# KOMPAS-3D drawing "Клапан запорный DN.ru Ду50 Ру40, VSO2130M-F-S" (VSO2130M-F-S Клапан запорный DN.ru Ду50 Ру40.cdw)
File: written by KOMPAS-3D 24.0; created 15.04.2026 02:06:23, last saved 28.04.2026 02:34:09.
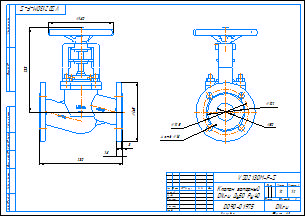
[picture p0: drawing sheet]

Document properties: Автор: DN.ru; Форматы листов документа: A3; Полное имя файла: VSO2130M-F-S Клапан запорный DN.ru Ду50 Ру40.m3d; Масса: 12; Наименование: Клапан запорный DN.ru Ду50 Ру40; Количество листов документа: 1; Примечание: D090-01975

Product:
- Part/product: Клапан запорный DN.ru Ду50 Ру40  | designation VSO2130M-F-S
    Масса: 12
    Раздел спецификации: Прочие изделия
    Примечание: D090-01975

Views: Вид 1, Вид:1, Проекционный вид 2
Referenced files in C:\Работа\VSO2130M-F-S Клапан запорный DN.ru\DN20\: VSO2130M-F-S DN20 PN40  Клапан запорный сильфонный DN.ru.m3d
Referenced files in C:\Работа\VSO2130M-F-S Клапан запорный DN.ru\DN50\: VSO2130M-F-S Клапан запорный DN.ru Ду50 Ру40.m3d
Referenced files in C:\Program Files\ASCON\KOMPAS-3D v24\Templates\: Чертеж_DN.ru.cdt
Referenced files in C:\Работа\ГОТОВЫЕ ИСХОДНИКИ\VSO2130M-F-S Клапан запорный сильфонный DN.ru Ду15-100 Ру40\DN50\: VSO2130M-F-S Клапан запорный DN.ru Ду50 Ру40.m3d
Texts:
  VSO2130M-F-S
  Чертеж_DN.ru.cdt
  Клапан запорный
  DN.ru Ду50 Ру40
  Клапан запорный DN.ru Ду50 Ру40
  VSO2130M-F-S  Клапан запорный DN.ru Ду50 Ру40
Dimensions and other numbers on the sheet: 0; 3; 2; 4; 165; 18; 233; 180; 230; 1; 5; 50; 102; 125; 4 отв.; 1:2; 12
